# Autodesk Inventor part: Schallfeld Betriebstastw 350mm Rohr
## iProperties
Shininess: 20.0
Length Units: 11269
Angle Units: 11279
Time Units: 11290
Mass Units: 11283
Length Display Precision: 2
Angle Display Precision: 2
Part Number: Schallfeld Betriebstastw 350mm Rohr
Material: Lexan (klar)
Document SubType Name: Modellieren
Description: Schallfeld 0,25 m
Checked By: Alves
Created: 2005-08
Designer: Klein
Manufacturer: Standard
Standards Organization: Custom
Density: 0.0
Volumn: 0.0
Area: 0.0
PropertySet Name: Model Information
Control State: 0
Master: False
Checked Out: False
Last Check In By: Kramp
Last Check In Date: 2005-08-11
ME: ST
Title: Schallfelder
Author: Klein
Comments: keine Bemerkung
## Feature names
1. Innenglocke [Revolution]
